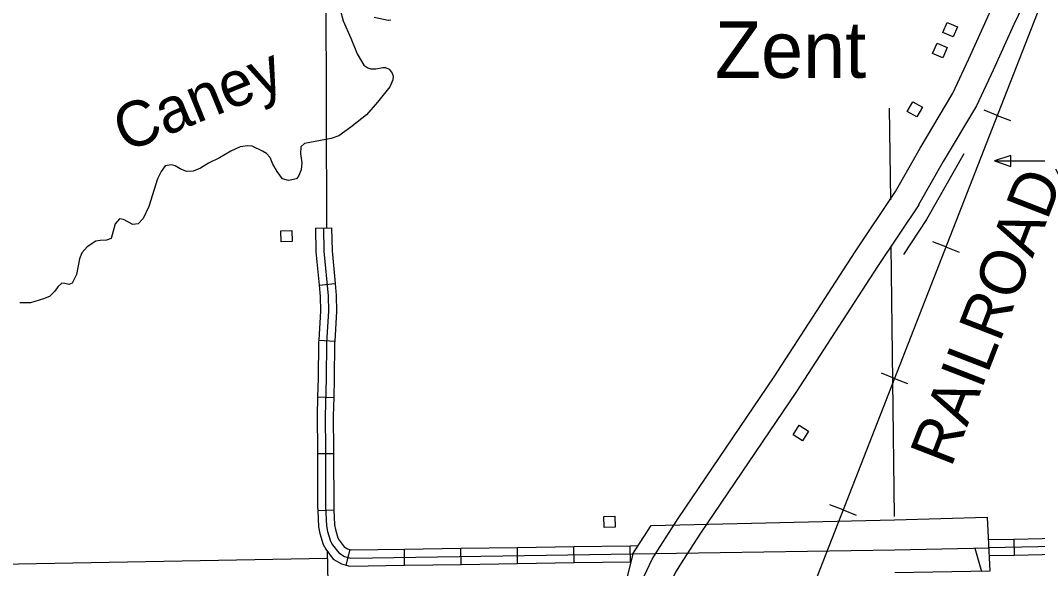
# Model space of a CAD drawing. Extents: x 1084508 to 1142749, y 1057638 to 1093403.
# Drawn here: x 1101810 to 1104795, y 1083898 to 1085507 of the extents above; entities that cross this region are included whole.
import ezdxf

# ---------------------------------------------------------------- set-up
doc = ezdxf.new("R2010")
doc.units = 0
for name, color, linetype in [('Level 15', 7, 'Continuous'), ('Level 24', 7, 'Continuous'), ('Level 32', 7, 'Continuous'), ('Level 34', 7, 'Continuous'), ('Level 35', 7, 'Continuous'), ('Level 40', 7, 'Continuous'), ('Level 5', 7, 'Continuous'), ('Level 56', 7, 'Continuous'), ('Level 57', 7, 'Continuous'), ('Level 6', 7, 'Continuous')]:
    doc.layers.add(name, color=color, linetype=linetype)

msp = doc.modelspace()

# ---------------------------------------------------------------- linework, layer by layer
at = {"layer": 'Level 15'}
for points in [[(1104377.2, 1085004.5), (1104449.7, 1085132.3), (1104545.7, 1085293.5), (1104593, 1085393.9), (1104653.6, 1085528.4), (1104692.9, 1085611.4)], [(1104762.7, 1085575.5), (1104724.9, 1085495.5), (1104664.3, 1085361), (1104615, 1085256.6), (1104517.5, 1085092.9), (1104445.5, 1084965.8)], [(1103207.5, 1082140.8), (1103444.8, 1083105), (1103629, 1083841.6), (1103639.7, 1083876), (1103663.8, 1083925.6), (1103687.3, 1083963.2), (1103739.7, 1084044.7), (1104021.3, 1084461.1), (1104259.6, 1084828), (1104377.2, 1085004.5)], [(1104445.6, 1084965.7), (1104325.1, 1084784.8), (1104086.7, 1084417.8), (1103805.2, 1084001.5), (1103753.6, 1083921.2), (1103732.6, 1083887.6), (1103712.8, 1083847), (1103704.6, 1083820.4), (1103521, 1083086.2), (1103283.8, 1082122.1)]]:
    msp.add_lwpolyline(points, dxfattribs=at)
at = {"layer": 'Level 32'}
for p, q in [((1102675.9, 1084897), (1102722.9, 1084897.9)), ((1102686.7, 1084729.9), (1102733.6, 1084734.4)), ((1102685.4, 1084568.2), (1102732.4, 1084565.3)), ((1102682.2, 1084401.9), (1102729.3, 1084400.3)), ((1102681.7, 1084235.3), (1102728.8, 1084235.4)), ((1102682.6, 1084068.7), (1102729.6, 1084070.6)), ((1104725.1, 1083983.8), (1104726, 1083936.7)), ((1102765.7, 1083908.4), (1102777.5, 1083954)), ((1102937.4, 1083907.9), (1102936.7, 1083954.9)), ((1103103.1, 1083910.4), (1103102.4, 1083957.4)), ((1103268.8, 1083912.9), (1103268.1, 1083959.9)), ((1103434.5, 1083915.4), (1103433.8, 1083962.4)), ((1103600.2, 1083917.8), (1103599.5, 1083964.9))]:
    msp.add_line(p, q, dxfattribs=at)
for points in [[(1102675.9, 1084897), (1102677.2, 1084828.1), (1102686.7, 1084729.9)], [(1102699.4, 1084897.4), (1102700.7, 1084829.4), (1102713.4, 1084698.5), (1102714.1, 1084653.4), (1102708.6, 1084561.9), (1102707.6, 1084455.8), (1102703.9, 1084345.7), (1102705.3, 1084244.7), (1102705.7, 1084080), (1102708, 1084023.6), (1102711.3, 1084007), (1102720, 1083978.3), (1102725.9, 1083968.1), (1102743.9, 1083943.7), (1102761.2, 1083933.9), (1102779.9, 1083929), (1103606.5, 1083941.5)], [(1102722.9, 1084897.9), (1102724.3, 1084830.8), (1102733.6, 1084734.4)], [(1102686.7, 1084729.9), (1102689.9, 1084697.1), (1102690.5, 1084654), (1102685.4, 1084568.2)], [(1102733.6, 1084734.4), (1102736.9, 1084699.8), (1102737.6, 1084652.9), (1102732.4, 1084565.3)], [(1102685.4, 1084568.2), (1102685, 1084562.8), (1102684, 1084456.3), (1102682.2, 1084401.9)], [(1102732.4, 1084565.3), (1102732.1, 1084561.1), (1102731.1, 1084455.3), (1102729.3, 1084400.3)], [(1102682.2, 1084401.9), (1102680.3, 1084346), (1102681.7, 1084244.5), (1102681.7, 1084235.3)], [(1102729.3, 1084400.3), (1102727.4, 1084345.5), (1102728.8, 1084244.9), (1102728.8, 1084235.4)], [(1102681.7, 1084235.3), (1102682.1, 1084079.5), (1102682.6, 1084068.7)], [(1102728.8, 1084235.4), (1102729.2, 1084080.5), (1102729.6, 1084070.6)], [(1102682.6, 1084068.7), (1102684.5, 1084020.8), (1102688.4, 1084001.3), (1102698.2, 1083968.9), (1102706.2, 1083955.1), (1102727.9, 1083925.8), (1102752.3, 1083911.8), (1102765.7, 1083908.4)], [(1102729.6, 1084070.6), (1102731.4, 1084026.4), (1102734.1, 1084012.8), (1102741.7, 1083987.8), (1102745.6, 1083981.1), (1102759.9, 1083961.7), (1102770.2, 1083955.9), (1102777.5, 1083954)], [(1104725.1, 1083983.8), (1104649.9, 1083982.2)], [(1106051.1, 1083987.4), (1104651, 1083958.7)], [(1104890.8, 1083987.2), (1104725.1, 1083983.8)], [(1102777.5, 1083954), (1102782.7, 1083952.6), (1102936.7, 1083954.9)], [(1102936.7, 1083954.9), (1103102.4, 1083957.4)], [(1103102.4, 1083957.4), (1103268.1, 1083959.9)], [(1103268.1, 1083959.9), (1103433.8, 1083962.4)], [(1103433.8, 1083962.4), (1103599.5, 1083964.9)], [(1103599.5, 1083964.9), (1103622.1, 1083965.3)], [(1104726, 1083936.7), (1104652, 1083935.2)], [(1104891.7, 1083940.1), (1104726, 1083936.7)], [(1102765.7, 1083908.4), (1102777.1, 1083905.5), (1102937.4, 1083907.9)], [(1102937.4, 1083907.9), (1103103.1, 1083910.4)], [(1103103.1, 1083910.4), (1103268.8, 1083912.9)], [(1103268.8, 1083912.9), (1103434.5, 1083915.4)], [(1103434.5, 1083915.4), (1103600.7, 1083917.9)]]:
    msp.add_lwpolyline(points, dxfattribs=at)
at = {"layer": 'Level 34'}
for points in [[(1103606.5, 1083941.5), (1104376.1, 1083953.1), (1104651, 1083958.7)], [(1104610.4, 1083957.9), (1104629.6, 1083889.6)]]:
    msp.add_lwpolyline(points, dxfattribs=at)
at = {"layer": 'Level 35'}
for points in [[(1102748.2, 1085539.2), (1102756.7, 1085506.3), (1102780, 1085454.7), (1102798.3, 1085409.3), (1102817.8, 1085375.2), (1102829.4, 1085367.7), (1102838.6, 1085365.1), (1102853.3, 1085364.9), (1102873.3, 1085369.3), (1102881.5, 1085368.6), (1102892.4, 1085364.1), (1102901.2, 1085352.4), (1102903.6, 1085343.7), (1102902.4, 1085332.6), (1102893.6, 1085312.2), (1102857.5, 1085267.1), (1102825.2, 1085229.9), (1102780, 1085193.9), (1102744.6, 1085168), (1102721.9, 1085160.4), (1102643.4, 1085145.6), (1102632.7, 1085136.4), (1102631.4, 1085115.9)], [(1102897, 1085507.9), (1102888.8, 1085506.7), (1102848, 1085515.3)], [(1102631.4, 1085115.9), (1102635.3, 1085088.6), (1102634, 1085068.8), (1102626.4, 1085049.6), (1102619.7, 1085042.5), (1102596.9, 1085037.1), (1102579.4, 1085041.7), (1102563.1, 1085063.9), (1102551.1, 1085085.2), (1102542.4, 1085104.5), (1102531.7, 1085116.5), (1102520.5, 1085123.4), (1102490.2, 1085137.6), (1102477.5, 1085138.9), (1102455.3, 1085135.7), (1102427.1, 1085123.2), (1102394.3, 1085104), (1102361.7, 1085088.2), (1102338.6, 1085073.1), (1102316.8, 1085064.3), (1102297, 1085064), (1102278.6, 1085071), (1102263.8, 1085080.4), (1102252.4, 1085083.5), (1102235.2, 1085080.2), (1102222.8, 1085064), (1102212.1, 1085041.7), (1102187.2, 1084960.6), (1102170.3, 1084925.5), (1102155.6, 1084910), (1102140, 1084907.6), (1102112.8, 1084922.3), (1102100.8, 1084924.8), (1102088.3, 1084909.6), (1102076.1, 1084866.4), (1102062.7, 1084862.2), (1102044.1, 1084861.4), (1102031.6, 1084859.1), (1102005.7, 1084842.9), (1101989.9, 1084824.5), (1101983.1, 1084807), (1101974.4, 1084761.4), (1101962.3, 1084735.5), (1101952.3, 1084732.1), (1101940.3, 1084734.9), (1101931.2, 1084735.3), (1101919.8, 1084725.2), (1101910.7, 1084712.6), (1101895.8, 1084697.1), (1101878.1, 1084689.6), (1101839.7, 1084678.4), (1101808.6, 1084677.8)]]:
    msp.add_lwpolyline(points, dxfattribs=at)
at = {"layer": 'Level 40'}
for p, q in [((1104676.2, 1085228), (1104637.6, 1085243.1)), ((1104676.2, 1085228), (1104714.8, 1085212.9)), ((1104525.4, 1084842.1), (1104486.8, 1084857.2)), ((1104525.4, 1084842.1), (1104564, 1084827)), ((1104374.6, 1084456.2), (1104336.1, 1084471.2)), ((1104374.6, 1084456.2), (1104413.2, 1084441.1)), ((1104223.9, 1084070.2), (1104185.3, 1084085.3)), ((1104223.9, 1084070.2), (1104262.5, 1084055.2))]:
    msp.add_line(p, q, dxfattribs=at)
for points in [[(1105593.6, 1087538.5), (1105266.5, 1086724.2), (1104945.2, 1085916.1), (1104652.3, 1085166.8), (1104226, 1084075.6), (1103955, 1083382.1), (1103584, 1082434), (1103293.5, 1081677.2), (1102955.6, 1080814.4), (1102738.3, 1080275.5)], [(1104945.2, 1085916.1), (1104652.3, 1085166.8), (1104226, 1084075.6), (1103955, 1083382.1), (1103584, 1082434), (1103293.5, 1081677.2), (1102955.6, 1080814.4)]]:
    msp.add_lwpolyline(points, dxfattribs=at)
at = {"layer": 'Level 5'}
for points in [[(1102692.6, 1087768.2), (1102706.5, 1085591.2), (1102708.3, 1084897.6)], [(1104363.7, 1084980.6), (1104360.4, 1085249)], [(1104374.9, 1084050.8), (1104365.3, 1084845.1)], [(1102710.3, 1083949.6), (1102727.3, 1083109.9)], [(1102710.8, 1083928), (1101643.3, 1083908.3)]]:
    msp.add_lwpolyline(points, dxfattribs=at)
at = {"layer": 'Level 56'}
for points in [[(1104529.4, 1085501.3), (1104559.5, 1085488.5), (1104546.7, 1085458.4), (1104516.6, 1085471.1)], [(1104499.4, 1085440.4), (1104529.5, 1085427.6), (1104516.7, 1085397.5), (1104486.6, 1085410.2)], [(1104440.1, 1085223.9), (1104411.8, 1085240.1), (1104428.1, 1085268.5), (1104456.4, 1085252.3)], [(1102574.7, 1084857.1), (1102573.8, 1084889.8), (1102606.5, 1084890.7), (1102607.5, 1084858.1)], [(1104105.1, 1084273.4), (1104077.3, 1084290.7), (1104094.6, 1084318.5), (1104122.4, 1084301.2)], [(1103522.4, 1084018.3), (1103521.4, 1084050.9), (1103554.2, 1084051.9), (1103555.1, 1084019.2)]]:
    msp.add_lwpolyline(points, close=True, dxfattribs=at)
at = {"layer": 'Level 57'}
for points in [[(1104578.3, 1085115.6), (1104468.9, 1084922.5), (1104400.7, 1084820)], [(1104667.7, 1085094.7), (1104836.5, 1085094.7), (1104991.7, 1084768.7)]]:
    msp.add_lwpolyline(points, dxfattribs=at)
msp.add_lwpolyline([(1104715.7, 1085078.7), (1104715.7, 1085110.7), (1104667.7, 1085094.7)], close=True, dxfattribs=at)
at = {"layer": 'Level 6'}
for points in [[(1103606.5, 1083941.5), (1103660.8, 1084024.6), (1104375, 1084041.4)], [(1104375, 1084041.4), (1104646.9, 1084048.8), (1104654.1, 1083890), (1104375.9, 1083885.3)], [(1103606.5, 1083941.5), (1103375.1, 1083005.9), (1103202.7, 1082262.9)]]:
    msp.add_lwpolyline(points, dxfattribs=at)

# ---------------------------------------------------------------- texts
at = {"layer": 'Level 24'}
msp.add_text('Zent', height=165.73, dxfattribs=at).set_placement((1103847.9, 1085338.4))
at = {"layer": 'Level 35'}
msp.add_text('Caney', height=132.58, rotation=22.174, dxfattribs=at).set_placement((1102117.4, 1085118.5))
at = {"layer": 'Level 40'}
msp.add_text('RAILROAD', height=132.58, rotation=68.7797, dxfattribs=at).set_placement((1104540.7, 1084192.2))

doc.saveas('drawing.dxf')
